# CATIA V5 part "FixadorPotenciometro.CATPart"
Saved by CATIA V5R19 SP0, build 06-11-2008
Part number: FixadorPotenciometro
Bounding box of the stored display mesh (mm): x -24.799 to -3.299, y 0 to 35, z 28.339 to 55.339
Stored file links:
  C:\Documents and Settings\Proprietário\Ambiente de trabalho\Coluna\SuportePotenciometro\FixadorPotenciometro.CATPart
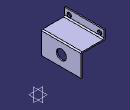
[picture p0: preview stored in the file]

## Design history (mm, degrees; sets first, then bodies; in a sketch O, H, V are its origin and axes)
Body1 (main body)
  Sketch1 on zx-plane, origin (0, 0, 0), H (-1, 0, 0), V (0, 0, 1)
    line L1 (23.7993, 48.3395) -> (3.2993, 48.3395)
    line L2 (3.2993, 48.3395) -> (3.2993, 28.3395)
    line L3 (3.2993, 28.3395) -> (4.2993, 28.3395)
    line L4 (4.2993, 28.3395) -> (4.2993, 47.3395)
    point P5 (4.2993, 47.3395)
    line L5 (24.7993, 55.3395) -> (24.7993, 47.3395)
    line L6 (24.7993, 47.3395) -> (4.2993, 47.3395)
    point P8 (4.2993, 47.3395)
    reference projected line E1 (24.7993, 10.9052) -> (24.7993, 45.9052) from edge of DatumCurve6
    line L7 (23.7993, 48.3395) -> (23.7993, 55.3395)
    line L8 (23.7993, 55.3395) -> (24.7993, 55.3395)
    reference projected line E2 (26.7993, 55.3395) -> (24.7993, 55.3395) from edge of DatumCurve8
    distance L2 L4 = 1
    distance L6 L1 = 1
    length L8 = 1
    length L7 = 7
    distance L2 L5 = 21.5
    length L2 = 20
    horizontal: L1 H, L3 H, L6 H, L8 H
    vertical: L2 V, L4 V, L5 V, L7 V
    coincidence: P8 L4, P5 P8, L5 E1, E2 L8
  Pad1: profile Sketch1, direction (0, 1, 0), length 35
  DatumCurve1
  DatumCurve2
  Sketch2 on face of Pad1 from Sketch1.L5, origin (-24.7993, 0, 0), H (0, -1, 0), V (0, 0, 1)
    projected circle E1 centre (-4, 51.3395) radius 2 from edge of DatumCurve1
    projected circle E2 centre (-31, 51.3395) radius 2 from edge of DatumCurve2
  Pocket1: profile Sketch2, direction (1, 0, 0), through (limit type 3)
  Sketch3 on face of Pad1 from Sketch1.L2, origin (-3.2993, 0, 0), H (0, 1, 0), V (0, 0, 1)
    circle A1 centre (17.5, 37.8395) radius 4.5
    point P1 (17.5, 37.8395)
    reference projected line E1 (0, 28.3395) -> (35, 28.3395) from edge [face of Pad1 from Sketch1.L3 | face of Pad1 from Sketch1.L2]
    reference projected line E2 (35, 48.3395) -> (35, 28.3395) from edge [face of Pad1 from Sketch1.L2 | end face of Pad1]
    radius A1 = 4.5
    distance E1 P1 = 9.5
    distance P1 E2 = 17.5
  Pocket2: profile Sketch3, direction (-1, 0, 0), through (limit type 3)
  Fillet1: radius 1, on edge [face of Pad1 from Sketch1.L2 | face of Pad1 from Sketch1.L1]; edge [face of Pad1 from Sketch1.L1 | face of Pad1 from Sketch1.L7]; edge [face of Pad1 from Sketch1.L6 | face of Pad1 from Sketch1.L4]; edge [face of Pad1 from Sketch1.L5 | face of Pad1 from Sketch1.L6]
  DatumCurve3 to DatumCurve8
